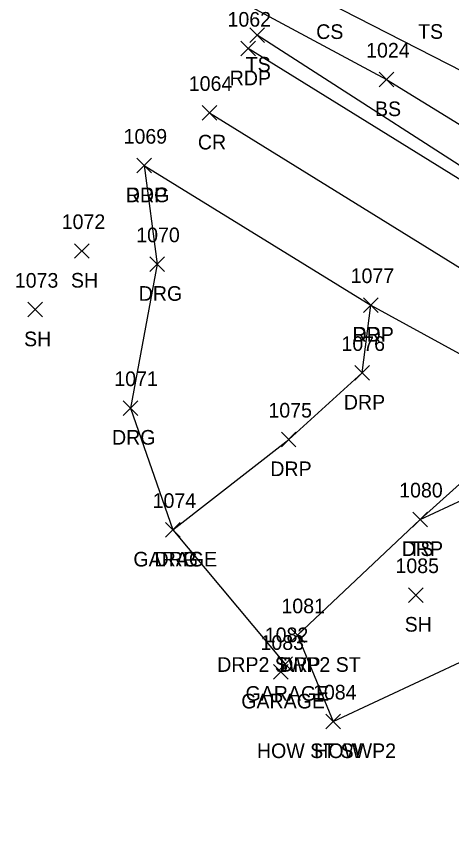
# Model space of a CAD drawing. Extents: x 1504228 to 1506103, y 437717 to 440106.
# Drawn here: x 1504984.3 to 1505043.8, y 438330.5 to 438441.9 of the extents above; entities that cross this region are included whole.
import ezdxf

# ---------------------------------------------------------------- set-up
doc = ezdxf.new("R2010")
doc.units = 0
for name, color, linetype in [('L_A', 7, 'Continuous'), ('L_I', 7, 'Continuous'), ('L_TIC', 7, 'Continuous'), ('LBC', 7, 'Continuous'), ('LELB', 7, 'Continuous'), ('P_A', 7, 'Continuous'), ('P_I', 7, 'Continuous'), ('P_TIC', 7, 'Continuous'), ('PET', 7, 'Continuous'), ('PRC', 7, 'Continuous'), ('R_A', 7, 'Continuous'), ('R_I', 7, 'Continuous'), ('R_TIC', 7, 'Continuous'), ('RDG', 7, 'Continuous'), ('RDP', 7, 'Continuous'), ('RSW', 7, 'Continuous')]:
    doc.layers.add(name, color=color, linetype=linetype)

msp = doc.modelspace()

# ---------------------------------------------------------------- linework, layer by layer
at = {"layer": 'L_TIC'}
for points in [[(1505016.23, 438438.34), (1505018.23, 438440.34)], [(1505018.23, 438438.34), (1505016.23, 438440.34)], [(1505033.88, 438432.26), (1505035.88, 438434.26)], [(1505035.88, 438432.26), (1505033.88, 438434.26)], [(1504992.26, 438408.84), (1504994.26, 438410.84)], [(1504994.26, 438408.84), (1504992.26, 438410.84)], [(1504985.85, 438400.83), (1504987.85, 438402.83)], [(1504987.85, 438400.83), (1504985.85, 438402.83)], [(1505038.49, 438372.18), (1505040.49, 438374.18)], [(1505040.49, 438372.18), (1505038.49, 438374.18)], [(1505004.69, 438370.75), (1505006.69, 438372.75)], [(1505006.69, 438370.75), (1505004.69, 438372.75)], [(1505037.89, 438361.85), (1505039.89, 438363.85)], [(1505039.89, 438361.85), (1505037.89, 438363.85)], [(1505020.02, 438352.41), (1505022.02, 438354.41)], [(1505022.02, 438352.41), (1505020.02, 438354.41)], [(1505019.44, 438351.36), (1505021.44, 438353.36)], [(1505021.44, 438351.36), (1505019.44, 438353.36)], [(1505026.62, 438344.58), (1505028.62, 438346.58)], [(1505028.62, 438344.58), (1505026.62, 438346.58)]]:
    msp.add_lwpolyline(points, dxfattribs=at)
at = {"layer": 'LBC'}
for points in [[(1505005.69, 438371.75), (1505021.02, 438353.41), (1505020.44, 438352.36)], [(1505027.62, 438345.58), (1505058.82, 438360.13), (1505059.31, 438358.93), (1505068.76, 438338.35), (1505069.11, 438337.41), (1505053.48, 438330.53)]]:
    msp.add_lwpolyline(points, dxfattribs=at)
at = {"layer": 'LELB'}
for points in [[(1505066.13, 438478.34), (1505082.79, 438430.57), (1505090.38, 438412.27), (1505093.43, 438405.26), (1505092.12, 438400.75), (1505084.32, 438400.96), (1505068.59, 438407.1), (1505055.45, 438414.73), (1505017.23, 438439.34)], [(1505057.76, 438475.63), (1505067.05, 438452.95), (1505078.01, 438425.75), (1505068.86, 438419.51), (1505047.43, 438433.25), (1505026.83, 438443.8), (1505009.49, 438446.93)], [(1505009.49, 438446.93), (1505034.88, 438433.26), (1505059.13, 438418.39), (1505073.11, 438411.36), (1505084.65, 438408.25), (1505088.77, 438405.58), (1505088.5, 438402.9), (1505084.32, 438400.96)], [(1505039.49, 438373.18), (1505053.23, 438379.53), (1505059.01, 438383.32), (1505062.62, 438372.64), (1505066.29, 438362.49)]]:
    msp.add_lwpolyline(points, dxfattribs=at)
at = {"layer": 'P_TIC'}
for points in [[(1505014.97, 438436.48), (1505016.97, 438438.48)], [(1505016.97, 438436.48), (1505014.97, 438438.48)], [(1505009.68, 438427.71), (1505011.68, 438429.71)], [(1505011.68, 438427.71), (1505009.68, 438429.71)], [(1505000.77, 438420.5), (1505002.77, 438422.5)], [(1505002.77, 438420.5), (1505000.77, 438422.5)], [(1505031.76, 438401.46), (1505033.76, 438403.46)], [(1505033.76, 438401.46), (1505031.76, 438403.46)]]:
    msp.add_lwpolyline(points, dxfattribs=at)
at = {"layer": 'PET'}
for points in [[(1505098.18, 438413.38), (1505097.4, 438406.33), (1505096.17, 438402.68), (1505093.78, 438398.47), (1505087.56, 438395.41), (1505081.78, 438397.94), (1505054.27, 438413.83), (1505015.97, 438437.48)], [(1505001.77, 438421.5), (1505032.76, 438402.46), (1505059.81, 438387.63), (1505089.41, 438366.8), (1505108.6, 438355.58), (1505130.11, 438339.58)]]:
    msp.add_lwpolyline(points, dxfattribs=at)
at = {"layer": 'PRC'}
msp.add_lwpolyline([(1505010.68, 438428.71), (1505047.73, 438405.8), (1505081.29, 438385.46), (1505105.54, 438371.01), (1505120.75, 438360.59)], dxfattribs=at)
at = {"layer": 'R_TIC'}
for points in [[(1505000.77, 438420.5), (1505002.77, 438422.5)], [(1505002.77, 438420.5), (1505000.77, 438422.5)], [(1505002.54, 438407.04), (1505004.54, 438409.04)], [(1505004.54, 438407.04), (1505002.54, 438409.04)], [(1505031.76, 438401.46), (1505033.76, 438403.46)], [(1505033.76, 438401.46), (1505031.76, 438403.46)], [(1505030.57, 438392.19), (1505032.57, 438394.19)], [(1505032.57, 438392.19), (1505030.57, 438394.19)], [(1504998.88, 438387.39), (1505000.88, 438389.39)], [(1505000.88, 438387.39), (1504998.88, 438389.39)], [(1505020.52, 438383.09), (1505022.52, 438385.09)], [(1505022.52, 438383.09), (1505020.52, 438385.09)], [(1505038.49, 438372.18), (1505040.49, 438374.18)], [(1505040.49, 438372.18), (1505038.49, 438374.18)], [(1505004.69, 438370.75), (1505006.69, 438372.75)], [(1505006.69, 438370.75), (1505004.69, 438372.75)], [(1505004.69, 438370.75), (1505006.69, 438372.75)], [(1505006.69, 438370.75), (1505004.69, 438372.75)], [(1505021.74, 438356.36), (1505023.74, 438358.36)], [(1505023.74, 438356.36), (1505021.74, 438358.36)], [(1505021.74, 438356.36), (1505023.74, 438358.36)], [(1505023.74, 438356.36), (1505021.74, 438358.36)], [(1505026.62, 438344.58), (1505028.62, 438346.58)], [(1505028.62, 438344.58), (1505026.62, 438346.58)]]:
    msp.add_lwpolyline(points, dxfattribs=at)
at = {"layer": 'RDG'}
msp.add_lwpolyline([(1505001.77, 438421.5), (1505003.54, 438408.04), (1504999.88, 438388.39), (1505005.69, 438371.75)], dxfattribs=at)
at = {"layer": 'RDP'}
for points in [[(1505005.69, 438371.75), (1505021.52, 438384.09), (1505031.57, 438393.19), (1505032.76, 438402.46)], [(1505059.81, 438387.63), (1505051.56, 438384.01), (1505039.49, 438373.18), (1505022.74, 438357.36)]]:
    msp.add_lwpolyline(points, dxfattribs=at)
at = {"layer": 'RSW'}
msp.add_lwpolyline([(1505022.74, 438357.36), (1505027.62, 438345.58)], dxfattribs=at)

# ---------------------------------------------------------------- texts
at = {"layer": 'L_A'}
for s, p in [('CS', (1505025.28, 438438.8)), ('TS', (1505039.21, 438438.82)), ('TS', (1505015.64, 438434.34)), ('BS', (1505033.32, 438428.26)), ('SH', (1504991.75, 438404.84)), ('SH', (1504985.34, 438396.83)), ('TS', (1505037.9, 438368.18)), ('GARAGE', (1505000.29, 438366.75)), ('SH', (1505037.38, 438357.85)), ('GARAGE', (1505015.62, 438348.41)), ('GARAGE', (1505015.04, 438347.36)), ('HOW', (1505025.01, 438340.58))]:
    msp.add_text(s, height=2, dxfattribs=at).set_placement(p)
at = {"layer": 'L_I'}
for s, p in [('1024', (1505032.11, 438436.26)), ('1072', (1504990.49, 438412.84)), ('1073', (1504984.08, 438404.83)), ('1080', (1505036.63, 438376.18)), ('1074', (1505002.92, 438374.75)), ('1085', (1505036.12, 438365.85)), ('1082', (1505018.25, 438356.41)), ('1083', (1505017.67, 438355.36)), ('1084', (1505024.85, 438348.58))]:
    msp.add_text(s, height=2, dxfattribs=at).set_placement(p)
at = {"layer": 'P_A'}
for s, p in [('RDP', (1505013.46, 438432.48)), ('CR', (1505009.11, 438423.71)), ('RDP', (1504999.26, 438416.5)), ('RDP', (1505030.25, 438397.46))]:
    msp.add_text(s, height=2, dxfattribs=at).set_placement(p)
at = {"layer": 'P_I'}
for s, p in [('1062', (1505013.16, 438440.48)), ('1064', (1505007.86, 438431.71)), ('1069', (1504998.95, 438424.5)), ('1077', (1505029.99, 438405.46))]:
    msp.add_text(s, height=2, dxfattribs=at).set_placement(p)
at = {"layer": 'R_A'}
for s, p in [('DRG', (1504999.26, 438416.5)), ('DRG', (1505001.02, 438403.04)), ('DRP', (1505030.25, 438397.46)), ('DRP', (1505029.06, 438388.19)), ('DRG', (1504997.37, 438383.39)), ('DRP', (1505019.01, 438379.09)), ('DRP', (1505036.98, 438368.18)), ('DRG', (1505003.18, 438366.75)), ('DRP', (1505003.18, 438366.75)), ('DRP2 SWP2 ST', (1505011.75, 438352.36)), ('DRP', (1505020.23, 438352.36)), ('HOW ST SWP2', (1505017.18, 438340.58))]:
    msp.add_text(s, height=2, dxfattribs=at).set_placement(p)
at = {"layer": 'R_I'}
for s, p in [('1069', (1504998.95, 438424.5)), ('1070', (1505000.68, 438411.04)), ('1077', (1505029.99, 438405.46)), ('1076', (1505028.74, 438396.19)), ('1071', (1504997.68, 438391.39)), ('1075', (1505018.75, 438387.09)), ('1080', (1505036.63, 438376.18)), ('1074', (1505002.92, 438374.75)), ('1074', (1505002.92, 438374.75)), ('1081', (1505020.53, 438360.36)), ('1081', (1505020.53, 438360.36)), ('1084', (1505024.85, 438348.58))]:
    msp.add_text(s, height=2, dxfattribs=at).set_placement(p)

doc.saveas('drawing.dxf')
